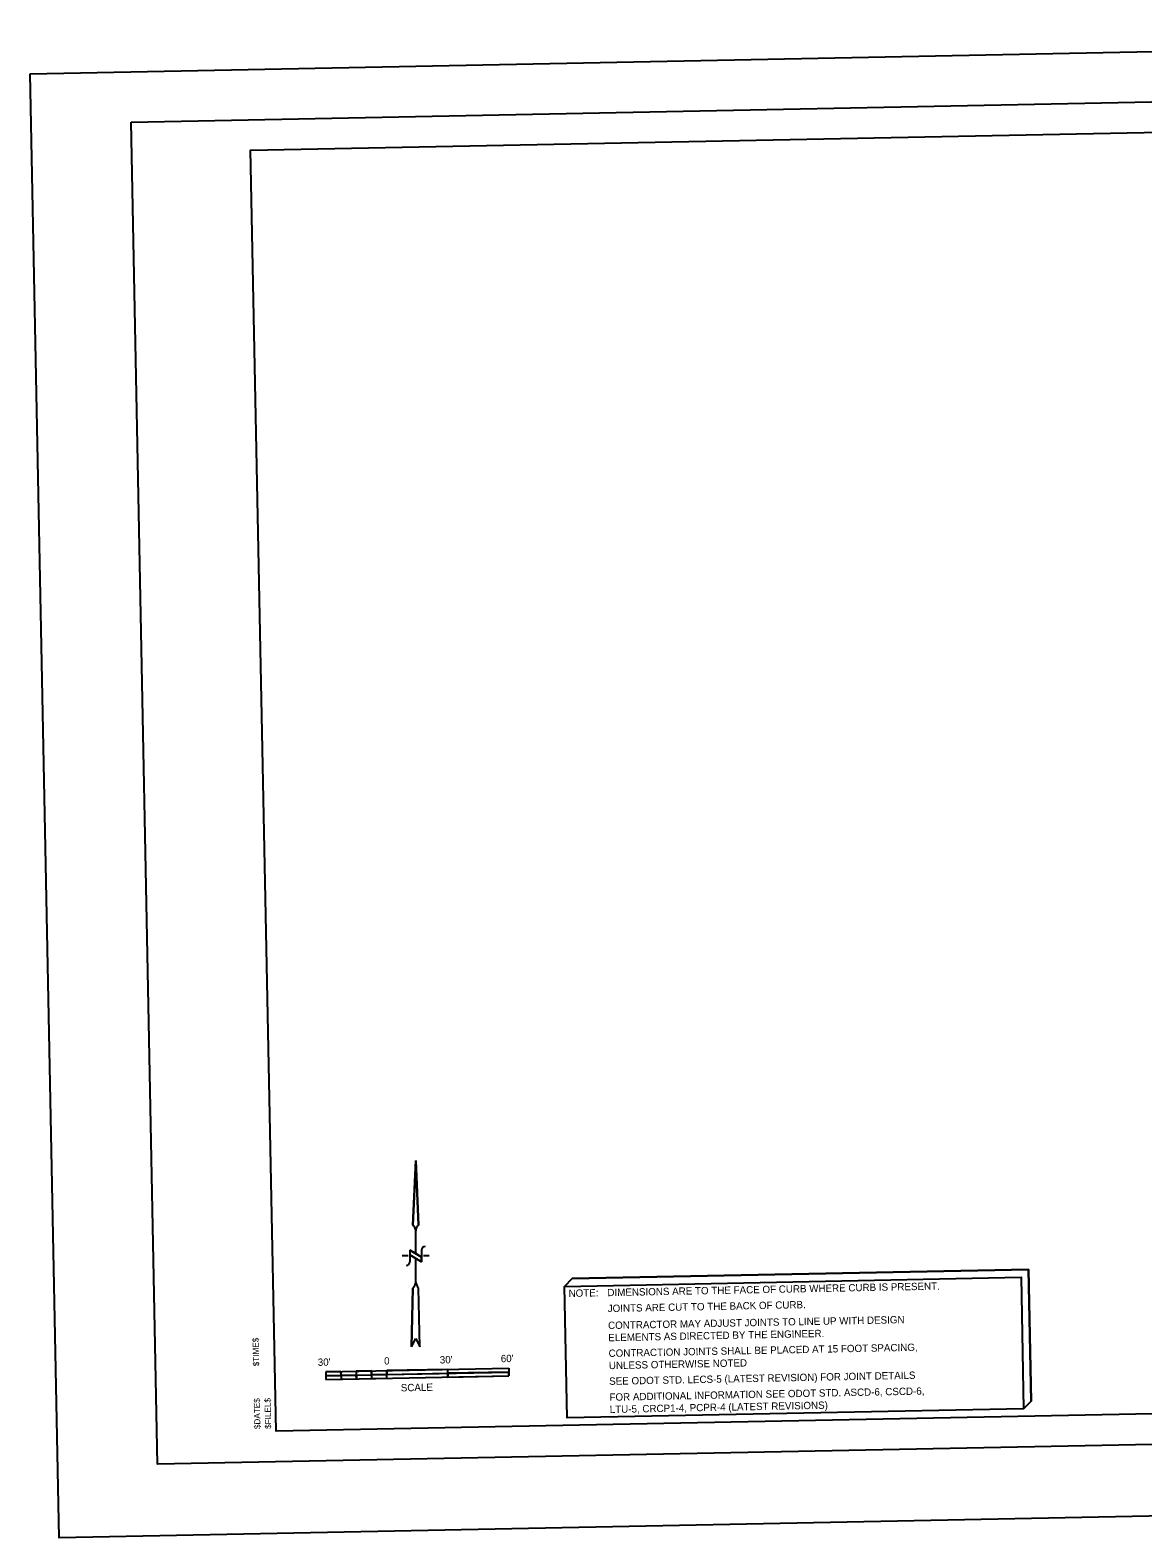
# Model space of a CAD drawing. Extents: x 2150263 to 2151357, y 141764 to 142505.
# Drawn here: x 2150263 to 2150810, y 141764 to 142505 of the extents above; entities that cross this region are included whole.
import ezdxf

# ---------------------------------------------------------------- set-up
doc = ezdxf.new("R2010")
doc.units = 0
for name, color, linetype in [('PR_Align_1_Leader', 7, 'Continuous'), ('PR_Align_1_PI_Curve', 7, 'Continuous'), ('PR_Align_Ramp_A_PI_Curve', 7, 'Continuous'), ('PR_Align_Ramp_B_PC', 7, 'Continuous'), ('PR_Align_Ramp_B_PI', 7, 'Continuous'), ('PR_Align_Ramp_G', 7, 'Continuous'), ('PR_Align_Ramp_G_Leader', 7, 'Continuous'), ('PR_Align_Ramp_G_Txt', 7, 'Continuous')]:
    doc.layers.add(name, color=color, linetype=linetype)

msp = doc.modelspace()

# ---------------------------------------------------------------- linework, layer by layer
at = {"layer": 'PR_Align_1_PI_Curve'}
msp.add_lwpolyline([(2150525.96, 141887.44), (2150529.64, 141891.27), (2150754.01, 141895.71), (2150755.29, 141831.04), (2150751.62, 141827.22)], dxfattribs=at)
msp.add_lwpolyline([(2150525.96, 141887.44), (2150750.34, 141891.89), (2150751.62, 141827.22), (2150527.24, 141822.77)], close=True, dxfattribs=at)
at = {"layer": 'PR_Align_Ramp_A_PI_Curve'}
msp.add_lwpolyline([(2150312.8, 142459.88), (2151332.6, 142480.09), (2151345.67, 141820.22), (2150325.87, 141800.01)], close=True, dxfattribs=at)
at = {"layer": 'PR_Align_Ramp_B_PC'}
for p, q in [((2150451.3, 141917.55), (2150452.75, 141949.28)), ((2150452.75, 141949.28), (2150451.3, 141917.55)), ((2150452.75, 141949.28), (2150454.19, 141917.55)), ((2150454.19, 141917.55), (2150452.75, 141949.28)), ((2150452.75, 141903.51), (2150452.75, 141914.74)), ((2150449, 141902.36), (2150446.13, 141902.36)), ((2150455.62, 141901.79), (2150449.87, 141905.24)), ((2150449.87, 141905.24), (2150455.62, 141901.79)), ((2150449.87, 141905.24), (2150449.87, 141899.48)), ((2150452.75, 141903.51), (2150449.87, 141905.24)), ((2150449.87, 141905.24), (2150449.87, 141902.94)), ((2150455.62, 141899.48), (2150449.87, 141902.94)), ((2150455.62, 141901.79), (2150452.75, 141903.51)), ((2150452.75, 141889.41), (2150452.75, 141901.21)), ((2150455.62, 141905.24), (2150455.62, 141899.48)), ((2150455.62, 141899.48), (2150455.62, 141901.79)), ((2150459.37, 141902.36), (2150456.49, 141902.36)), ((2150450.73, 141857.75), (2150451.31, 141886.53)), ((2150451.31, 141886.53), (2150450.73, 141857.75)), ((2150454.76, 141857.75), (2150454.19, 141886.53)), ((2150454.76, 141857.75), (2150454.19, 141886.53)), ((2150450.73, 141857.75), (2150452.75, 141861.78)), ((2150450.73, 141857.75), (2150452.75, 141861.78)), ((2150452.75, 141861.78), (2150454.76, 141857.75)), ((2150452.75, 141861.78), (2150454.76, 141857.75))]:
    msp.add_line(p, q, dxfattribs=at)
for points in [[(2150449.87, 141902.94), (2150452.75, 141901.21), (2150455.62, 141899.48)], [(2150452.75, 141889.41), (2150452.75, 141889.41), (2150452.74, 141889.41)]]:
    msp.add_lwpolyline(points, dxfattribs=at)
for centre, radius, start, end in [((2150449.29, 141914.74), 3.45, 0, 54.38016), ((2150449.29, 141914.74), 3.45, 0, 54.38016), ((2150456.2, 141914.74), 3.45, 125.61984, 180), ((2150456.2, 141914.74), 3.45, 125.61984, 180), ((2150457.35, 141905.24), 1.73, 90, 180), ((2150448.14, 141899.48), 1.73, 270, 0), ((2150447.73, 141890.11), 5.06, 314.95671, 352.41889), ((2150447.73, 141890.11), 5.06, 314.95671, 352.059), ((2150457.76, 141890.11), 5.06, 187.58111, 225.04329), ((2150457.76, 141890.11), 5.06, 187.941, 225.04329)]:
    msp.add_arc(centre, radius, start, end, dxfattribs=at)
at = {"layer": 'PR_Align_Ramp_B_PI'}
for p, q in [((2150408.49, 141845.4), (2150498.47, 141847.19)), ((2150415.99, 141845.55), (2150408.49, 141845.4)), ((2150408.49, 141845.4), (2150408.56, 141841.65)), ((2150408.49, 141845.4), (2150408.53, 141843.53)), ((2150408.53, 141843.53), (2150416.03, 141843.68)), ((2150408.53, 141843.53), (2150416.03, 141843.68)), ((2150408.56, 141841.65), (2150498.55, 141843.44)), ((2150415.99, 141845.55), (2150416.06, 141841.8)), ((2150416.03, 141843.68), (2150415.99, 141845.55)), ((2150416.03, 141843.68), (2150423.52, 141843.82)), ((2150423.52, 141843.82), (2150416.03, 141843.68)), ((2150416.03, 141843.68), (2150416.06, 141841.8)), ((2150416.06, 141841.8), (2150423.56, 141841.95)), ((2150430.99, 141845.85), (2150423.49, 141845.7)), ((2150423.49, 141845.7), (2150423.56, 141841.95)), ((2150423.49, 141845.7), (2150423.56, 141841.95)), ((2150423.49, 141845.7), (2150423.52, 141843.82)), ((2150423.52, 141843.82), (2150431.02, 141843.97)), ((2150423.52, 141843.82), (2150431.02, 141843.97)), ((2150423.56, 141841.95), (2150423.52, 141843.82)), ((2150430.99, 141845.85), (2150431.06, 141842.1)), ((2150431.02, 141843.97), (2150430.99, 141845.85)), ((2150431.02, 141843.97), (2150438.52, 141844.12)), ((2150438.52, 141844.12), (2150431.02, 141843.97)), ((2150431.02, 141843.97), (2150431.06, 141842.1)), ((2150431.06, 141842.1), (2150438.56, 141842.25)), ((2150468.48, 141846.59), (2150438.48, 141846)), ((2150438.52, 141844.12), (2150438.48, 141846)), ((2150438.48, 141846), (2150438.52, 141844.12)), ((2150438.52, 141844.12), (2150498.51, 141845.31)), ((2150438.52, 141844.12), (2150468.52, 141844.72)), ((2150438.56, 141842.25), (2150438.52, 141844.12)), ((2150438.56, 141842.25), (2150438.52, 141844.12)), ((2150468.52, 141844.72), (2150468.48, 141846.59)), ((2150468.52, 141844.72), (2150468.48, 141846.59)), ((2150498.51, 141845.31), (2150468.52, 141844.72)), ((2150468.55, 141842.84), (2150468.52, 141844.72)), ((2150468.52, 141844.72), (2150468.55, 141842.84)), ((2150468.55, 141842.84), (2150498.55, 141843.44)), ((2150498.47, 141847.19), (2150498.51, 141845.31)), ((2150498.51, 141845.31), (2150498.55, 141843.44)), ((2150498.55, 141843.44), (2150498.51, 141845.31))]:
    msp.add_line(p, q, dxfattribs=at)
at = {"layer": 'PR_Align_Ramp_G'}
msp.add_line((2150529.64, 141891.27), (2150525.96, 141887.44), dxfattribs=at)
for points in [[(2150525.96, 141887.44), (2150750.34, 141891.89), (2150751.62, 141827.22)], [(2150751.62, 141827.22), (2150755.29, 141831.04), (2150754.01, 141895.71), (2150529.64, 141891.27)]]:
    msp.add_lwpolyline(points, dxfattribs=at)
at = {"layer": 'PR_Align_Ramp_G_Leader'}
msp.add_lwpolyline([(2150263.19, 142483.65), (2151342.98, 142505.05), (2151357.24, 141785.19), (2150277.46, 141763.79)], close=True, dxfattribs=at)
at = {"layer": 'PR_Align_Ramp_G_Txt'}
msp.add_lwpolyline([(2151328.88, 141834.89), (2150384.06, 141816.16), (2150371.58, 142446.04), (2151316.4, 142464.76)], close=True, dxfattribs=at)

# ---------------------------------------------------------------- texts
at = {"layer": 'PR_Align_1_Leader'}
for s, p in [('$TIME$', (2150375.78, 141848.17)), ('$FILEL$', (2150381.72, 141817.39)), ('$DATE$', (2150376.4, 141817.28))]:
    msp.add_text(s, height=3, rotation=91.13538, dxfattribs=at).set_placement(p)
at = {"layer": 'PR_Align_1_PI_Curve'}
for s, p in [('NOTE:', (2150527.92, 141882.22)), ('DIMENSIONS ARE TO THE FACE OF CURB WHERE CURB IS PRESENT.', (2150547.02, 141882.59)), ('JOINTS ARE CUT TO THE BACK OF CURB.', (2150547.18, 141874.77)), ('CONTRACTOR MAY ADJUST JOINTS TO LINE UP WITH DESIGN', (2150547.34, 141866.44)), ('ELEMENTS AS DIRECTED BY THE ENGINEER.', (2150547.46, 141860.43)), ('CONTRACTION JOINTS SHALL BE PLACED AT 15 FOOT SPACING,', (2150547.61, 141852.73)), ('UNLESS OTHERWISE NOTED', (2150547.73, 141846.72)), ('SEE ODOT STD. LECS-5 (LATEST REVISION) FOR JOINT DETAILS', (2150547.88, 141839)), ('FOR ADDITIONAL INFORMATION SEE ODOT STD. ASCD-6, CSCD-6,', (2150548.04, 141831.16)), ('LTU-5, CRCP1-4, PCPR-4 (LATEST REVISIONS)', (2150548.16, 141825.15))]:
    msp.add_text(s, height=3.6, rotation=1.13538, dxfattribs=at).set_placement(p)
at = {"layer": 'PR_Align_Ramp_B_PI'}
for s, p in [("30'", (2150404.62, 141848.33)), ('0', (2150437.24, 141848.97)), ("30'", (2150464.61, 141849.51)), ("60'", (2150494.6, 141850.11)), ('SCALE', (2150445.43, 141835.78))]:
    msp.add_text(s, height=3.6, rotation=1.13538, dxfattribs=at).set_placement(p)

doc.saveas('drawing.dxf')
